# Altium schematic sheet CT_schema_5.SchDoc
size 255 x 245 mm
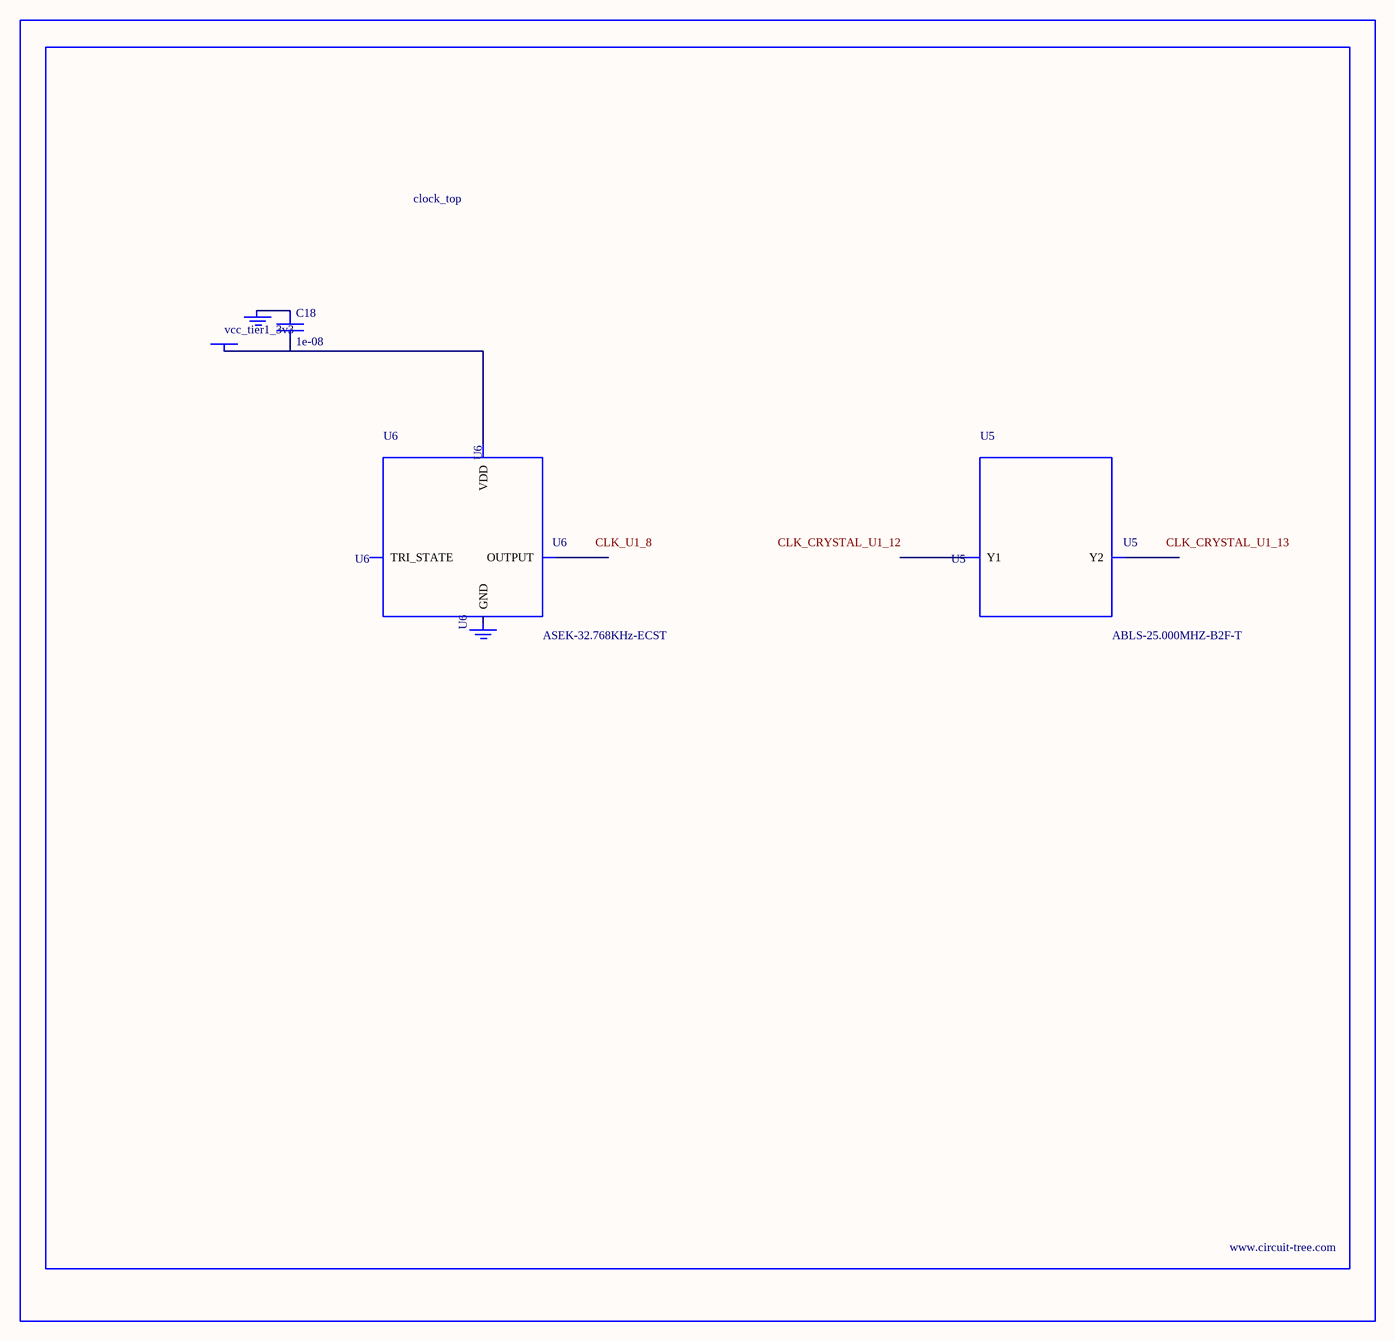
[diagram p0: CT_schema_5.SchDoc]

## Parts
BORDER4  (no value)
C18  1e-08  [C0402]
GND_INSTANCE_4_0  (no value)
GND_INSTANCE_4_1  (no value)
POWER_INSTANCE_4_0  vcc_tier1_3v3
U5  ABLS-25.000MHZ-B2F-T  [ABLS-25.000MHZ-B2F-T]
U6  ASEK-32.768KHz-ECST  [ASEK]

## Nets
NetC18_1: C18.1 GND_INSTANCE_4_0.0(GND)
NetC18_2: C18.2 POWER_INSTANCE_4_0.0(PWR) U6.4(VDD)

Not connected (* = marked no-connect by the designer): GND_INSTANCE_4_1 0(GND); U5 1(Y1) 2(Y2); U6 1(TRI_STATE) 2(GND) 3(OUTPUT)

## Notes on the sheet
- Labels drawn without touching a wire or pin: CLK_CRYSTAL_U1_12, CLK_CRYSTAL_U1_13, CLK_U1_8

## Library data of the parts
BORDER4 = BORDER_PAGE4
C18 = C0402C103K3RAC
GND_INSTANCE_4_0 GND_INSTANCE_4_1 = GND
POWER_INSTANCE_4_0 = PWR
